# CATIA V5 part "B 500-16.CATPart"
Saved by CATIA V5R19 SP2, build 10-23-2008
Part number: B 500-16
Bounding box of the stored display mesh (mm): x -18.951 to 18.951, y -18.952 to 18.952, z 0 to 82
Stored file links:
  C:\Users\Bora\Desktop\3D Katı model\B serisi\B 500\B 500-16.CATPart
  C:\Program Files\Dassault Systemes\B19\intel_a\reffiles\standard\MetricThickPitch.txt
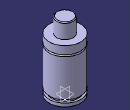
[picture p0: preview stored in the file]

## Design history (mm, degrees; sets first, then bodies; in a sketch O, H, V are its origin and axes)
Body1 (main body)
  Sketch1 on yz-plane, origin (0, 0, 0), H (0, 1, 0), V (0, 0, 1)
    point P3 (10, 81)
    point P5 (10, 81)
    point P7 (19, 54.5)
    point P8 (19, 52.5)
    point P12 (19, 52.5)
    point P13 (19, 54.5)
    line L1 (19, 0) -> (19, 4)
    line L2 (10, 81) -> (10, 64)
    arc A1 centre (9, 81) radius 1 from (10, 81) to (9, 82) ccw
    arc A2 centre (19, 53.5) radius 1 from (19, 54.5) to (19, 52.5) ccw
    line L3 (16.5, 7.5) -> (16.5, 4)
    line L4 (19, 7.5) -> (19, 52.5)
    line L5 (19, 54.5) -> (19, 64)
    line L6 (9, 82) -> (0, 82)
    point P15 (0, 82)
    line L7 (10, 64) -> (19, 64)
    line L8 (0, 0) -> (19, 0)
    line L9 (16.5, 7.5) -> (19, 7.5)
    line L10 (16.5, 4) -> (19, 4)
    coincidence: P15 V, P3 P5, P7 P13, P8 P12
    tangency: L6 A1
    horizontal: L7 H, L8 H, L9 H, L10 H
  Shaft1: profile Sketch1, axis Sketch1.V, angle 360
  Sketch2 on face of Shaft1 from Sketch1.L8, origin (0, 0, 0), H (1, 0, 0), V (0, -1, 0)
    point P1 (0, 0)
  Hole1: placed by Sketch2, at (0, 0, 0) direction (0, 0, 1), diameter 6.647, depth 7, threaded "M8", thread diameter 8, thread depth 7, pitch 1.25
